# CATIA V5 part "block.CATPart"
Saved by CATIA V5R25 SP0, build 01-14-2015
Part number: block
Bounding box of the stored display mesh (mm): x 0 to 17.5, y 0 to 10, z -10 to 0
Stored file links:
  C:\Users\Aidata\Downloads\chapter4\chapter4\block.CATPart
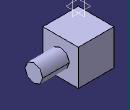
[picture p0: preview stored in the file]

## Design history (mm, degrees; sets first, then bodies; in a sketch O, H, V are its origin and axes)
Body1 (main body)
  Sketch1 on yz-plane, origin (0, 0, 0), H (0, 1, 0), V (0, 0, 1)
    line L1 (0, 0) -> (10, 0)
    line L2 (10, 0) -> (10, -10)
    line L3 (10, -10) -> (0, -10)
    line L4 (0, -10) -> (0, 0)
    distance L1 L3 = 10
    distance L2 L4 = 10
    horizontal: L1 H, L3 H
    vertical: L2 V, L4 V
  Pad1: profile Sketch1, direction (1, 0, 0), length 10
  Sketch2 on end face of Pad1, origin (10, 0, 0), H (0, 1, 0), V (0, 0, 1)
    axis line L1 (5, 6.9287) -> (5, -16.9287)
    reference projected line E1 (0, 0) -> (0, -10) from edge [face of Pad1 from Sketch1.L4 | end face of Pad1]
    circle A1 centre (5, -5) radius 2.5
    point P3 (5, -5)
    reference projected line E2 (10, 0) -> (0, 0) from edge [face of Pad1 from Sketch1.L1 | end face of Pad1]
    distance E1 L1 = 5
    radius A1 = 2.5
    distance P3 E2 = 5
    vertical: L1 V
    midpoint: P3 L1
  Pad2: profile Sketch2, direction (1, 0, 0), length 7.5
